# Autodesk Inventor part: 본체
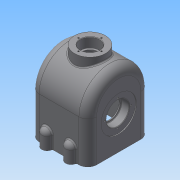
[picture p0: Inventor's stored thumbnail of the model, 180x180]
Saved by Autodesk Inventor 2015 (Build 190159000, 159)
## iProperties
Created: 2023-03
Part Number: 본체
Material: 일반
Document SubType Name: Modeling
Designer: home
Density: 1 g/cm^3
Appearance: 기본값
Mass: 844.028 g
Surface Area: 1798.4 cm^2
Volume: 844.028 cm^3
Author: home
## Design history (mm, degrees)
sketch "스케치1"
  geometry: L1 (-70, 0)-(-70, -94); L2 (-70, -94)-(70, -94); L3 (70, -94)-(70, 0); A1 r 70 centre (0, 0) between (70, 0) and (-70, 0); 1 further point
  constraints: 6 end point, 2 perpendicular, 2 point on circle, 2 tangent, 1 centre point, 1 coincident, 1 vertical
  dimensions: "d0" = 140 diameter of A1; "d1" = 94 distance from line of L2 point (0, 0)
extrude "돌출1" new body sketch "스케치1" stored distance "d2" = 130; taper "d3" = 0 deg
fillet "모깎기1" dims "d4" = 20
feature "쉘1" dims "d5" = 10
sketch "스케치2"
  geometry: L1 (94, -50)-(94, 50) reference; C1 r 40 at (19, 0); 1 further point
  constraints: 1 centre point, 1 horizontal alignment
  dimensions: "d6" = 80 diameter of C1; "d7" = 75 distance from line of C1.centre L1
extrude "돌출2" cut sketch "스케치2" distance "d8" = 2; taper "d9" = 0 deg
node "작업 평면1"
sketch "스케치3"
  geometry: L1 (-94, -50)-(-94, 50) reference; C1 r 30 at (-19, 0); 1 further point
  constraints: 1 centre point, 1 horizontal alignment
  dimensions: "d11" = 75 distance from line of C1.centre L1; "d12" = 60 diameter of C1
extrude "돌출3" join sketch "스케치3" distance "d13" = 12; taper "d14" = 45 deg
sketch "스케치4"
  geometry: C1 r 40 at (0, 0) reference; C2 r 26 at (0, 0); 1 further point
  constraints: 1 centre point, 1 coincident
  dimensions: "d15" = 52 diameter of C2
extrude "돌출4" cut sketch "스케치4" distance "d16" = 18; taper "d17" = 0 deg
sketch "스케치5"
  geometry: C1 r 26 at (0, 0) reference; C2 r 23 at (0, 0); 1 further point
  constraints: 1 centre point, 1 coincident
  dimensions: "d18" = 46 diameter of C2
extrude "돌출5" cut sketch "스케치5" distance "d19" = 18; taper "d20" = 0 deg
sketch "스케치6"
  geometry: L1 (0, 0)-(-30, 0); C1 r 26 at (0, 0) reference; 1 further point
  constraints: 2 end point, 1 horizontal
  dimensions: "d21" = 30 distance of L1.start L1.end
hole "구멍1" sketch "스케치6" at (-30, 0) diameter "d22" = 3.242; stored, may be unused: countersink angle "d26" = 90 deg, drill point angle "d28" = 118 deg; dims "d23" = 8, "d24" = 4, "d25" = 2, "d27" = 10
node "작업 평면2"
sketch "스케치7"
  geometry: C1 r 35 at (45, -70); 1 further point
  constraints: 1 centre point, 1 coincident
  dimensions: "d33" = 70 diameter of C1
extrude "돌출6" join sketch "스케치7" stored distance "d34" = 18; taper "d35" = 0 deg
sketch "스케치8"
  geometry: C1 r 21.5 at (0, 0); 1 further point
  constraints: 1 centre point, 1 coincident
  dimensions: "d36" = 43 diameter of C1
extrude "돌출7" cut sketch "스케치8" distance "d37" = 22; taper "d38" = 0 deg
sketch "스케치9"
  geometry: C1 r 17 at (0, 0); 1 further point
  constraints: 1 centre point, 1 coincident
  dimensions: "d39" = 34 diameter of C1
extrude "돌출8" cut sketch "스케치9" distance "d40" = 22; taper "d41" = 0 deg
sketch "스케치10"
  geometry: L1 (0, 0)-(-26, 0)
  constraints: 2 end point, 1 horizontal
  dimensions: "d42" = 26 distance of L1.start L1.end
hole "구멍2" sketch "스케치10" at (-26, 0) diameter "d43" = 3.242; stored, may be unused: countersink angle "d47" = 90 deg, drill point angle "d49" = 118 deg; dims "d44" = 8, "d45" = 4, "d46" = 2, "d48" = 10
sketch "스케치11"
  geometry: L1 (0, -140)-(90, -140) reference; A1 r 12 centre (18, -140) between (6, -140) and (30, -140); 1 further point
  constraints: 2 point on circle, 2 point on line, 1 centre point, 1 horizontal alignment
  dimensions: "d53" = 24 diameter of A1; "d54" = 27 horizontal distance of A1.centre point (45, -70)
extrude "돌출9" join sketch "스케치11" distance "d55" = 40; taper "d56" = 0 deg
fillet "모깎기2" dims "d57" = 12
hole "구멍3" diameter "d60" = 10.106; stored, may be unused: countersink angle "d64" = 90 deg, drill point angle "d66" = 118 deg; dims "d58" = 10, "d59" = 10, "d61" = 24, "d62" = 4, "d63" = 2, "d65" = 26
hole "구멍4" diameter "d69" = 10.106; stored, may be unused: countersink angle "d73" = 90 deg, drill point angle "d75" = 118 deg; dims "d67" = 10, "d68" = 10, "d70" = 24, "d71" = 4, "d72" = 2, "d74" = 26
hole "구멍5" diameter "d78" = 10.106; stored, may be unused: countersink angle "d82" = 90 deg, drill point angle "d84" = 118 deg; dims "d76" = 10, "d77" = 10, "d79" = 24, "d80" = 4, "d81" = 2, "d83" = 26
hole "구멍6" diameter "d87" = 10.106; stored, may be unused: countersink angle "d91" = 90 deg, drill point angle "d93" = 118 deg; dims "d85" = 10, "d86" = 10, "d88" = 24, "d89" = 4, "d90" = 2, "d92" = 26
chamfer "모따기1" distance "d94" = 1; stored, may be unused: second distance "d95" = 2, angle "d96" = 45 deg
fillet "모깎기3" dims "d97" = 1
sketch "스케치12"
  geometry: L1 (-15, -94)-(15, -94) reference; L2 (22.5, 84)-(-22.5, 84) reference; 3 further points
  constraints: 1 midpoint, 1 vertical alignment, 1 other
  dimensions: "d98" = 8 distance from line of point (0, 76) L2
feature "엠보싱1" sketch "스케치12" dims "d0" = 140, "d1" = 94, "d99" = 0.5, "d100" = 0
fillet "모깎기4" dims "d101" = 3
fillet "모깎기5" dims "d102" = 3
fillet "모깎기6" dims "d103" = 3
node "솔리드1"
pattern_circular "원형 패턴1" dims angle "d30" = 360 deg
mirror "대칭1"
pattern_circular "원형 패턴2" dims angle "d51" = 360 deg
mirror "대칭2"
mirror "대칭3"
other parameters: "d10" = 12, "d32" = -178
